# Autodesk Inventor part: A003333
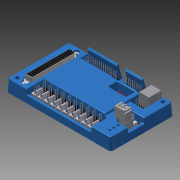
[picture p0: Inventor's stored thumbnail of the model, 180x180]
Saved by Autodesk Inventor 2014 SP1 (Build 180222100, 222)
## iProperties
Category: Control System
Company: Autodesk, Inc.
Created: 2012-11
Part Number: A003333
Document SubType Name: Modeling
Density: 1.48838 g/cm^3
Vendor: Total Electronics / AndyMark
Description: Digital Sidecar
Project: FIRST
Catalog Web Link: http://www.andymark.com/FIRST-Choice-p/fc13-098.htm
Material: Generic
Appearance: Default
Mass: 113.398 g
Surface Area: 837.282 cm^2
Volume: 76.1889 cm^3
Title: Digital Sidecar
Author: Autodesk, Inc.
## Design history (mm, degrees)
derived "Sidecar Rev5p2 Assembly.iam"
body "Solid1"
node "Sidecar Rev5 Bottom.ipt:1"
node "Sidecar Rev5 PCB Assembly.iam:1::Sidecar Rev5 Board.ipt:1"
node "Sidecar Rev5 PCB Assembly.iam:1::RP22.ipt:1"
node "Sidecar Rev5 PCB Assembly.iam:1::RP21.ipt:1"
node "Sidecar Rev5 PCB Assembly.iam:1::RP20.ipt:1"
node "Sidecar Rev5 PCB Assembly.iam:1::RP19.ipt:1"
node "Sidecar Rev5 PCB Assembly.iam:1::RP18.ipt:1"
node "Sidecar Rev5 PCB Assembly.iam:1::RP17.ipt:1"
node "Sidecar Rev5 PCB Assembly.iam:1::RP16.ipt:1"
node "Sidecar Rev5 PCB Assembly.iam:1::RP15.ipt:1"
node "Sidecar Rev5 PCB Assembly.iam:1::RP14.ipt:1"
node "Sidecar Rev5 PCB Assembly.iam:1::RP13.ipt:1"
node "Sidecar Rev5 PCB Assembly.iam:1::RP8.ipt:1"
node "Sidecar Rev5 PCB Assembly.iam:1::RP4.ipt:1"
node "Sidecar Rev5 PCB Assembly.iam:1::CB2.ipt:1"
node "Sidecar Rev5 PCB Assembly.iam:1::C14.iam:1::588375968.ipt:1"
node "Sidecar Rev5 PCB Assembly.iam:1::C14.iam:1::588375712.ipt:1"
node "Sidecar Rev5 PCB Assembly.iam:1::U7.ipt:1"
node "Sidecar Rev5 PCB Assembly.iam:1::Q4.ipt:1"
node "Sidecar Rev5 PCB Assembly.iam:1::D25.iam:1::588376736.ipt:1"
node "Sidecar Rev5 PCB Assembly.iam:1::D25.iam:1::588376480.ipt:1"
node "Sidecar Rev5 PCB Assembly.iam:1::U6.ipt:1"
node "Sidecar Rev5 PCB Assembly.iam:1::U5.ipt:1"
node "Sidecar Rev5 PCB Assembly.iam:1::R13.ipt:1"
node "Sidecar Rev5 PCB Assembly.iam:1::R15.ipt:1"
node "Sidecar Rev5 PCB Assembly.iam:1::R14.ipt:1"
node "Sidecar Rev5 PCB Assembly.iam:1::R10.ipt:1"
node "Sidecar Rev5 PCB Assembly.iam:1::R12.ipt:1"
node "Sidecar Rev5 PCB Assembly.iam:1::R11.ipt:1"
node "Sidecar Rev5 PCB Assembly.iam:1::Q3.ipt:1"
node "Sidecar Rev5 PCB Assembly.iam:1::L2.ipt:1"
node "Sidecar Rev5 PCB Assembly.iam:1::L1.ipt:1"
node "Sidecar Rev5 PCB Assembly.iam:1::D30.iam:1::588380320.ipt:1"
node "Sidecar Rev5 PCB Assembly.iam:1::D30.iam:1::588380064.ipt:1"
node "Sidecar Rev5 PCB Assembly.iam:1::D32.ipt:1"
node "Sidecar Rev5 PCB Assembly.iam:1::D29.ipt:1"
node "Sidecar Rev5 PCB Assembly.iam:1::D27.iam:1::588381344.ipt:1"
node "Sidecar Rev5 PCB Assembly.iam:1::D27.iam:1::588381088.ipt:1"
node "Sidecar Rev5 PCB Assembly.iam:1::C12.ipt:1"
node "Sidecar Rev5 PCB Assembly.iam:1::C9.iam:1::587502784.ipt:1"
node "Sidecar Rev5 PCB Assembly.iam:1::C9.iam:1::587502528.ipt:1"
node "Sidecar Rev5 PCB Assembly.iam:1::C7.ipt:1"
node "Sidecar Rev5 PCB Assembly.iam:1::D11.iam:1::587504832.ipt:1"
node "Sidecar Rev5 PCB Assembly.iam:1::D11.iam:1::587504576.ipt:1"
node "Sidecar Rev5 PCB Assembly.iam:1::D12.iam:1::587505344.ipt:1"
node "Sidecar Rev5 PCB Assembly.iam:1::D12.iam:1::587505088.ipt:1"
node "Sidecar Rev5 PCB Assembly.iam:1::J25.iam:1::587529152.ipt:1"
node "Sidecar Rev5 PCB Assembly.iam:1::J25.iam:1::587528896.ipt:1"
node "Sidecar Rev5 PCB Assembly.iam:1::J25.iam:1::587528640.ipt:1"
node "Sidecar Rev5 PCB Assembly.iam:1::J25.iam:1::587528384.ipt:1"
node "Sidecar Rev5 PCB Assembly.iam:1::J25.iam:1::587528128.ipt:1"
node "Sidecar Rev5 PCB Assembly.iam:1::J25.iam:1::587527872.ipt:1"
node "Sidecar Rev5 PCB Assembly.iam:1::J25.iam:1::587527616.ipt:1"
node "Sidecar Rev5 PCB Assembly.iam:1::J25.iam:1::587527360.ipt:1"
node "Sidecar Rev5 PCB Assembly.iam:1::J25.iam:1::587527104.ipt:1"
node "Sidecar Rev5 PCB Assembly.iam:1::J25.iam:1::587526848.ipt:1"
node "Sidecar Rev5 PCB Assembly.iam:1::J25.iam:1::587526592.ipt:1"
node "Sidecar Rev5 PCB Assembly.iam:1::J25.iam:1::587526336.ipt:1"
node "Sidecar Rev5 PCB Assembly.iam:1::J25.iam:1::587526080.ipt:1"
node "Sidecar Rev5 PCB Assembly.iam:1::J25.iam:1::587525824.ipt:1"
node "Sidecar Rev5 PCB Assembly.iam:1::J25.iam:1::587525568.ipt:1"
node "Sidecar Rev5 PCB Assembly.iam:1::J25.iam:1::587525312.ipt:1"
node "Sidecar Rev5 PCB Assembly.iam:1::J25.iam:1::587525056.ipt:1"
node "Sidecar Rev5 PCB Assembly.iam:1::J25.iam:1::587524800.ipt:1"
node "Sidecar Rev5 PCB Assembly.iam:1::J25.iam:1::587524544.ipt:1"
node "Sidecar Rev5 PCB Assembly.iam:1::J25.iam:1::587524288.ipt:1"
node "Sidecar Rev5 PCB Assembly.iam:1::J25.iam:1::587524032.ipt:1"
node "Sidecar Rev5 PCB Assembly.iam:1::J25.iam:1::587523776.ipt:1"
node "Sidecar Rev5 PCB Assembly.iam:1::J25.iam:1::587523520.ipt:1"
node "Sidecar Rev5 PCB Assembly.iam:1::J25.iam:1::587523264.ipt:1"
node "Sidecar Rev5 PCB Assembly.iam:1::J25.iam:1::587523008.ipt:1"
node "Sidecar Rev5 PCB Assembly.iam:1::J25.iam:1::587522752.ipt:1"
node "Sidecar Rev5 PCB Assembly.iam:1::J25.iam:1::587522496.ipt:1"
node "Sidecar Rev5 PCB Assembly.iam:1::J25.iam:1::587522240.ipt:1"
node "Sidecar Rev5 PCB Assembly.iam:1::J25.iam:1::587521984.ipt:1"
node "Sidecar Rev5 PCB Assembly.iam:1::J25.iam:1::587521728.ipt:1"
node "Sidecar Rev5 PCB Assembly.iam:1::J25.iam:1::587521472.ipt:1"
node "Sidecar Rev5 PCB Assembly.iam:1::J25.iam:1::587521216.ipt:1"
node "Sidecar Rev5 PCB Assembly.iam:1::J25.iam:1::587520960.ipt:1"
node "Sidecar Rev5 PCB Assembly.iam:1::J25.iam:1::587520704.ipt:1"
node "Sidecar Rev5 PCB Assembly.iam:1::J25.iam:1::587520448.ipt:1"
node "Sidecar Rev5 PCB Assembly.iam:1::J25.iam:1::587520192.ipt:1"
node "Sidecar Rev5 PCB Assembly.iam:1::J25.iam:1::587519936.ipt:1"
node "Sidecar Rev5 PCB Assembly.iam:1::J25.iam:1::587519680.ipt:1"
node "Sidecar Rev5 PCB Assembly.iam:1::J25.iam:1::587519424.ipt:1"
node "Sidecar Rev5 PCB Assembly.iam:1::J25.iam:1::587519168.ipt:1"
node "Sidecar Rev5 PCB Assembly.iam:1::J25.iam:1::587518912.ipt:1"
node "Sidecar Rev5 PCB Assembly.iam:1::J25.iam:1::587518656.ipt:1"
node "Sidecar Rev5 PCB Assembly.iam:1::J25.iam:1::587518400.ipt:1"
node "Sidecar Rev5 PCB Assembly.iam:1::Q2.ipt:1"
node "Sidecar Rev5 PCB Assembly.iam:1::R1.ipt:1"
node "Sidecar Rev5 PCB Assembly.iam:1::R2.ipt:1"
node "Sidecar Rev5 PCB Assembly.iam:1::R5.ipt:1"
node "Sidecar Rev5 PCB Assembly.iam:1::R7.ipt:1"
node "Sidecar Rev5 PCB Assembly.iam:1::RP1.ipt:1"
node "Sidecar Rev5 PCB Assembly.iam:1::RP9.ipt:1"
node "Sidecar Rev5 PCB Assembly.iam:1::RP10.ipt:1"
node "Sidecar Rev5 PCB Assembly.iam:1::RP11.ipt:1"
node "Sidecar Rev5 PCB Assembly.iam:1::RP12.ipt:1"
node "Sidecar Rev5 PCB Assembly.iam:1::U1.ipt:1"
node "Sidecar Rev5 PCB Assembly.iam:1::U3.ipt:1"
node "Sidecar Rev5 PCB Assembly.iam:1::HiTechnic_RJ_Plug.ipt:1"
node "Sidecar Rev5 PCB Assembly.iam:1::D1.iam:1::587622272.ipt:1"
node "Sidecar Rev5 PCB Assembly.iam:1::D1.iam:1::587622016.ipt:1"
node "Sidecar Rev5 PCB Assembly.iam:1::D2.iam:1::587622784.ipt:1"
node "Sidecar Rev5 PCB Assembly.iam:1::D2.iam:1::587622528.ipt:1"
node "Sidecar Rev5 PCB Assembly.iam:1::D3.iam:1::587623296.ipt:1"
node "Sidecar Rev5 PCB Assembly.iam:1::D3.iam:1::587623040.ipt:1"
node "Sidecar Rev5 PCB Assembly.iam:1::D4.iam:1::587623808.ipt:1"
node "Sidecar Rev5 PCB Assembly.iam:1::D4.iam:1::587623552.ipt:1"
node "Sidecar Rev5 PCB Assembly.iam:1::D5.iam:1::587624320.ipt:1"
node "Sidecar Rev5 PCB Assembly.iam:1::D5.iam:1::587624064.ipt:1"
node "Sidecar Rev5 PCB Assembly.iam:1::D6.iam:1::587624832.ipt:1"
node "Sidecar Rev5 PCB Assembly.iam:1::D6.iam:1::587624576.ipt:1"
node "Sidecar Rev5 PCB Assembly.iam:1::D7.iam:1::587625344.ipt:1"
node "Sidecar Rev5 PCB Assembly.iam:1::D7.iam:1::587625088.ipt:1"
node "Sidecar Rev5 PCB Assembly.iam:1::D8.iam:1::587625856.ipt:1"
node "Sidecar Rev5 PCB Assembly.iam:1::D8.iam:1::587625600.ipt:1"
node "Sidecar Rev5 PCB Assembly.iam:1::D9.iam:1::587626368.ipt:1"
node "Sidecar Rev5 PCB Assembly.iam:1::D9.iam:1::587626112.ipt:1"
node "Sidecar Rev5 PCB Assembly.iam:1::D10.iam:1::587626880.ipt:1"
node "Sidecar Rev5 PCB Assembly.iam:1::D10.iam:1::587626624.ipt:1"
node "Sidecar Rev5 PCB Assembly.iam:1::D13.iam:1::587627392.ipt:1"
node "Sidecar Rev5 PCB Assembly.iam:1::D13.iam:1::587627136.ipt:1"
node "Sidecar Rev5 PCB Assembly.iam:1::D14.iam:1::587627904.ipt:1"
node "Sidecar Rev5 PCB Assembly.iam:1::D14.iam:1::587627648.ipt:1"
node "Sidecar Rev5 PCB Assembly.iam:1::D16.iam:1::587628416.ipt:1"
node "Sidecar Rev5 PCB Assembly.iam:1::D16.iam:1::587628160.ipt:1"
node "Sidecar Rev5 PCB Assembly.iam:1::D18.iam:1::587628928.ipt:1"
node "Sidecar Rev5 PCB Assembly.iam:1::D18.iam:1::587628672.ipt:1"
node "Sidecar Rev5 PCB Assembly.iam:1::J21.iam:1::587635328.ipt:1"
node "Sidecar Rev5 PCB Assembly.iam:1::J21.iam:1::587635072.ipt:1"
node "Sidecar Rev5 PCB Assembly.iam:1::J21.iam:1::587634816.ipt:1"
node "Sidecar Rev5 PCB Assembly.iam:1::J21.iam:1::587634560.ipt:1"
node "Sidecar Rev5 PCB Assembly.iam:1::J21.iam:1::587634304.ipt:1"
node "Sidecar Rev5 PCB Assembly.iam:1::J21.iam:1::587634048.ipt:1"
node "Sidecar Rev5 PCB Assembly.iam:1::J21.iam:1::587633792.ipt:1"
node "Sidecar Rev5 PCB Assembly.iam:1::J21.iam:1::587633536.ipt:1"
node "Sidecar Rev5 PCB Assembly.iam:1::J21.iam:1::587633280.ipt:1"
node "Sidecar Rev5 PCB Assembly.iam:1::J21.iam:1::587633024.ipt:1"
node "Sidecar Rev5 PCB Assembly.iam:1::J21.iam:1::587632768.ipt:1"
node "Sidecar Rev5 PCB Assembly.iam:1::J21.iam:1::587632512.ipt:1"
node "Sidecar Rev5 PCB Assembly.iam:1::J21.iam:1::587632256.ipt:1"
node "Sidecar Rev5 PCB Assembly.iam:1::J21.iam:1::587632000.ipt:1"
node "Sidecar Rev5 PCB Assembly.iam:1::J21.iam:1::587631744.ipt:1"
node "Sidecar Rev5 PCB Assembly.iam:1::J21.iam:1::587631488.ipt:1"
node "Sidecar Rev5 PCB Assembly.iam:1::J21.iam:1::587631232.ipt:1"
node "Sidecar Rev5 PCB Assembly.iam:1::J21.iam:1::587630976.ipt:1"
node "Sidecar Rev5 PCB Assembly.iam:1::J21.iam:1::587630720.ipt:1"
node "Sidecar Rev5 PCB Assembly.iam:1::J21.iam:1::587630464.ipt:1"
node "Sidecar Rev5 PCB Assembly.iam:1::J21.iam:1::587630208.ipt:1"
node "Sidecar Rev5 PCB Assembly.iam:1::J21.iam:1::587629952.ipt:1"
node "Sidecar Rev5 PCB Assembly.iam:1::J21.iam:1::587629696.ipt:1"
node "Sidecar Rev5 PCB Assembly.iam:1::J21.iam:1::587629440.ipt:1"
node "Sidecar Rev5 PCB Assembly.iam:1::J21.iam:1::587629184.ipt:1"
node "Sidecar Rev5 PCB Assembly.iam:1::RP3.ipt:1"
node "Sidecar Rev5 PCB Assembly.iam:1::RP5.ipt:1"
node "Sidecar Rev5 PCB Assembly.iam:1::U4.ipt:1"
node "Sidecar Rev5 PCB Assembly.iam:1::U2.ipt:1"
node "Sidecar Rev5 PCB Assembly.iam:1::RP6.ipt:1"
node "Sidecar Rev5 PCB Assembly.iam:1::RP7.ipt:1"
node "Sidecar Rev5 PCB Assembly.iam:1::RP2.ipt:1"
node "Sidecar Rev5 PCB Assembly.iam:1::CB1.iam:1::587638144.ipt:1"
node "Sidecar Rev5 PCB Assembly.iam:1::CB1.iam:1::587637888.ipt:1"
node "Sidecar Rev5 PCB Assembly.iam:1::CB1.iam:1::587637632.ipt:1"
node "Sidecar Rev5 PCB Assembly.iam:1::D15.iam:1::587643264.ipt:1"
node "Sidecar Rev5 PCB Assembly.iam:1::D15.iam:1::587643008.ipt:1"
node "Sidecar Rev5 PCB Assembly.iam:1::D17.ipt:1"
node "Sidecar Rev5 PCB Assembly.iam:1::J23.iam:1::587642752.ipt:1"
node "Sidecar Rev5 PCB Assembly.iam:1::J23.iam:1::587642496.ipt:1"
node "Sidecar Rev5 PCB Assembly.iam:1::J23.iam:1::587642240.ipt:1"
node "Sidecar Rev5 PCB Assembly.iam:1::J23.iam:1::587641984.ipt:1"
node "Sidecar Rev5 PCB Assembly.iam:1::J23.iam:1::587641728.ipt:1"
node "Sidecar Rev5 PCB Assembly.iam:1::J23.iam:1::587641472.ipt:1"
node "Sidecar Rev5 PCB Assembly.iam:1::J23.iam:1::587641216.ipt:1"
node "Sidecar Rev5 PCB Assembly.iam:1::J23.iam:1::587640960.ipt:1"
node "Sidecar Rev5 PCB Assembly.iam:1::J23.iam:1::587640704.ipt:1"
node "Sidecar Rev5 PCB Assembly.iam:1::Q1.ipt:1"
node "Sidecar Rev5 PCB Assembly.iam:1::R3.ipt:1"
node "Sidecar Rev5 PCB Assembly.iam:1::R4.ipt:1"
node "Sidecar Rev5 PCB Assembly.iam:1::Molex KK 2 Pin.ipt:1"
node "Sidecar Rev5 PCB Assembly.iam:1::734-132:1"
node "Sidecar Rev5 PCB Assembly.iam:1::DB37.ipt:1"
node "Sidecar Rev5 PCB Assembly.iam:1::Jumper 2 Pin.ipt:2"
node "Sidecar Rev5 PCB Assembly.iam:1::Molex KK 3 Pin.ipt:1"
node "Sidecar Rev5 PCB Assembly.iam:1::Jumper 2 Pin.ipt:1"
node "Sidecar Rev5 PCB Assembly.iam:1::Molex KK 3 Pin.ipt:2"
node "Sidecar Rev5 PCB Assembly.iam:1::Jumper 2 Pin.ipt:3"
node "Sidecar Rev5 PCB Assembly.iam:1::Molex KK 3 Pin.ipt:3"
node "Sidecar Rev5 PCB Assembly.iam:1::Jumper 2 Pin.ipt:4"
node "Sidecar Rev5 PCB Assembly.iam:1::Molex KK 3 Pin.ipt:4"
node "Sidecar Rev5 PCB Assembly.iam:1::Jumper 2 Pin.ipt:5"
node "Sidecar Rev5 PCB Assembly.iam:1::Molex KK 3 Pin.ipt:5"
node "Sidecar Rev5 PCB Assembly.iam:1::Jumper 2 Pin.ipt:6"
node "Sidecar Rev5 PCB Assembly.iam:1::Molex KK 3 Pin.ipt:6"
node "Sidecar Rev5 PCB Assembly.iam:1::Jumper 2 Pin.ipt:7"
node "Sidecar Rev5 PCB Assembly.iam:1::Molex KK 3 Pin.ipt:7"
node "Sidecar Rev5 PCB Assembly.iam:1::Jumper 2 Pin.ipt:8"
node "Sidecar Rev5 PCB Assembly.iam:1::Molex KK 3 Pin.ipt:8"
node "Sidecar Rev5 PCB Assembly.iam:1::Jumper 2 Pin.ipt:9"
node "Sidecar Rev5 PCB Assembly.iam:1::Molex KK 3 Pin.ipt:9"
node "Sidecar Rev5 PCB Assembly.iam:1::Jumper 2 Pin.ipt:10"
node "Sidecar Rev5 PCB Assembly.iam:1::Molex KK 3 Pin.ipt:10"
node "Sidecar Rev5 PCB Assembly.iam:1::Jumper 2 Pin.ipt:11"
node "Sidecar Rev5p2 Top.ipt:1"
node "734-102:1"
node "Sidecar Rev5p2 Assembly.iam_Bodies"
